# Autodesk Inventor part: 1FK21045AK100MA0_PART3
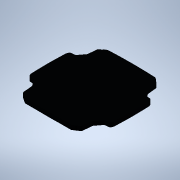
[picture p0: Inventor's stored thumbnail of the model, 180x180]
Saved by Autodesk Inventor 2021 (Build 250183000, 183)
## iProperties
Created: 2025-04
Part Number: 1FK21045AK100MA0_PART3
Material: Generic
Catalog Web Link: www.3dfindit.com
Description: -Servo synchronous motor
Document SubType Name: Modeling
Designer: psAdmin
Mass: 21.7019 g
Surface Area: 120.085 cm^2
Volume: 21.7019 cm^3
Density: 1 g/cm^3
Appearance: PSOLRGB-38-46-56
Category: PARTsolutions
Title: 1FK21045AK100MA0_PART3
Author: Cadenas PARTsolutions
Comments: Servo synchronous motor
Sending System: PARTsolutions
Preprocessor: ST-DEVELOPER v19.3
PSOL_IDENT_0: {$CADENAS_DATA/23d-libs/siemens_ag/_cat_/e0/5f/1fk21045ak100ma0.prj},213 {VTYP=3D},{NB=1FK21045AK100
PSOL_IDENT_1: MA0_PART3},{LINA=1FK21045AK100MA0_PART3},{NN=1FK21045AK100MA0_PART3},{NOPRJ=TRUE},{DATE=19.08.2025 1
PSOL_IDENT_2: 4:01:03},{GEOMDATE=30.07.2025 02:01:57},{VERSION=},{LINEID=10},{WBVAR=},{WBNUMERIC=}  {NB=1FK21045AK
PSOL_IDENT_3: 100MA0_PART3},{LINA=1FK21045AK100MA0_PART3},{KT=DUMMY},{PREVIEW=../../../_pool_/0f/2c/p_d211_xx_0043
PSOL_IDENT_4: 8j.png},{DESCSHORT=SIMOTICS S-1FK2 HD, SINAMICS S210 3AC 400V-480V, 1.7 Nm, 6000 rpm},{DESCLONG=SIMO
PSOL_IDENT_5: TICS S-1FK2 HD servo motor M0=2.4 Nm; PN = 1.07 kW at nN=6000 rpm (380-480 V); PN = 0.75 kW at nN=30
PSOL_IDENT_6: 00 rpm (200-240 V); with holding brake; degree of protection IP64; cylindrical shaft D19x40mm; absol
PSOL_IDENT_7: ute encoder 22-bit + 12-bit multiturn (encoder AM22DQC); with OCC interface; plug size M17, rotatabl
PSOL_IDENT_8: e; SIMOTICS S-1FK2 servomotorfor a wide range of uses in industrial environments. SIMOTICS S‑1FK2 se
PSOL_IDENT_9: rvomotors are compact synchronous motors with a high dynamic performance that set themselves apart a
PSOL_IDENT_10: s a result of their high power density, degree of protection and overload capability. The motors are
PSOL_IDENT_11: available in two variants: as High Dynamic variant (highest dynamic performance as a result of the
PSOL_IDENT_12: low intrinsic moment of inertia for applications demanding a high dynamic performance with low moved
PSOL_IDENT_13: masses) - and as Compact variant (precise and stable closed-loop control for medium up to large mov
PSOL_IDENT_14: ed masses as a result of a medium intrinsic moment of inertia). SIMOTICSS‑1FK2 servomotors fully exp
PSOL_IDENT_15: loit their strengths in a system with the SINAMICSS210 frequency converter and simple connection usi
PSOL_IDENT_16: ng the one cable connection (OCC). Advantages include the short control and positioning times, fast
PSOL_IDENT_17: and precise correction of disturbing quantities as well as stable control with a high dynamic perfor
PSOL_IDENT_18: mance. The servo motors can be configured to address a wide range of requirements. For example with
PSOL_IDENT_19: and without holding brake, IP64 or IP65 degree of protection, singleturn or multiturn absolute encod
PSOL_IDENT_20: ers - to name just a few. Further, the servomotors are available in different shaft heights extendin
PSOL_IDENT_21: g from 20 to 100. A shaft sealing ring is available to achieve an IP65 degree of protection and for
PSOL_IDENT_22: subsequent mounting at the motor or as spare part. SIMOTICS - the optimum motor for each and every m
PSOL_IDENT_23: otion control application.},{INTNO=804766807114},{SUPPLIERALTNO=1FK2104-5AK10-0MA0},{MANUID=1FK21045
PSOL_IDENT_24: AK100MA0},{MANUNAME=Siemens},{MANUTYPEDESC=Synchronous motor 1FK2-HD 2,39 Nm},{AAU732=SIMOTICS},{AAO
PSOL_IDENT_25: 057=S-1FK2},{AAU734=SIMOTICS S-1FK2 HD servo motor M0=2.4 Nm; PN = 1.07 kW at nN=6000 rpm (380-480 V
PSOL_IDENT_26: ); PN = 0.75 kW at nN=3000 rpm (200-240 V); with holding brake; degree of protection IP64; cylindric
PSOL_IDENT_27: al shaft D19x40mm; absolute encoder 22-bit + 12-bit multiturn (encoder AM22DQC); with OCC interface;
PSOL_IDENT_28: plug size M17, rotatable;},{AAW338=Synchronous motor 1FK2-HD 2,39 Nm},{AAO742=SIMOTICS},{AAO663=404
PSOL_IDENT_29: 2948691236},{NOCUPEROU=1},{PRICEQUANTITY=1},{QUANTITYMIN=1},{QUANTITYINT=1},{CTN=85015100},{COO=DE},
PSOL_IDENT_30: {AAO676=1FK2104-5AK10-0MA0},{AAO677=Siemens AG},{ORDERUNIT=C62},{CONTENTUNIT=C62}
NB: 1FK21045AK100MA0_PART3
NT: Servo synchronous motor
NBSYN: $MANUID._PART3
LINA: 1FK21045AK100MA0_PART3
CATALOG: SIEMENS
PREVIEW: ../../../_pool_/0f/2c/p_d211_xx_00438j.png
DESCSHORT: SIMOTICS S-1FK2 HD, SINAMICS S210 3AC 400V-480V, 1.7 Nm, 6000 rpm
DESCLONG: SIMOTICS S-1FK2 HD servo motor M0=2.4 Nm; PN = 1.07 kW at nN=6000 rpm (380-480 V); PN = 0.75 kW at nN=3000 rpm (200-240 V); with holding brake; degree of protec
INTNO: 804766807114
SUPPLIERALTNO: 1FK2104-5AK10-0MA0
MANUID: 1FK21045AK100MA0
MANUNAME: Siemens
MANUTYPEDESC: Synchronous motor 1FK2-HD 2,39 Nm
AAU732: SIMOTICS
AAO057: S-1FK2
AAU734: SIMOTICS S-1FK2 HD servo motor M0=2.4 Nm; PN = 1.07 kW at nN=6000 rpm (380-480 V); PN = 0.75 kW at nN=3000 rpm (200-240 V); with holding brake; degree of protec
AAW338: Synchronous motor 1FK2-HD 2,39 Nm
AAO742: SIMOTICS
AAO663: 4042948691236.0
NOCUPEROU: 1
PRICEQUANTITY: 1
QUANTITYMIN: 1
QUANTITYINT: 1
CTN: 85015100
COO: DE
ARTICLENO: 1FK21045AK100MA0_PART3
BOMINFO: 1FK21045AK100MA0_PART3
CREATOR: CADENAS GmbH
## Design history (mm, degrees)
feature "2025_04_17_15_45_15_0043"
body "Solid1"
